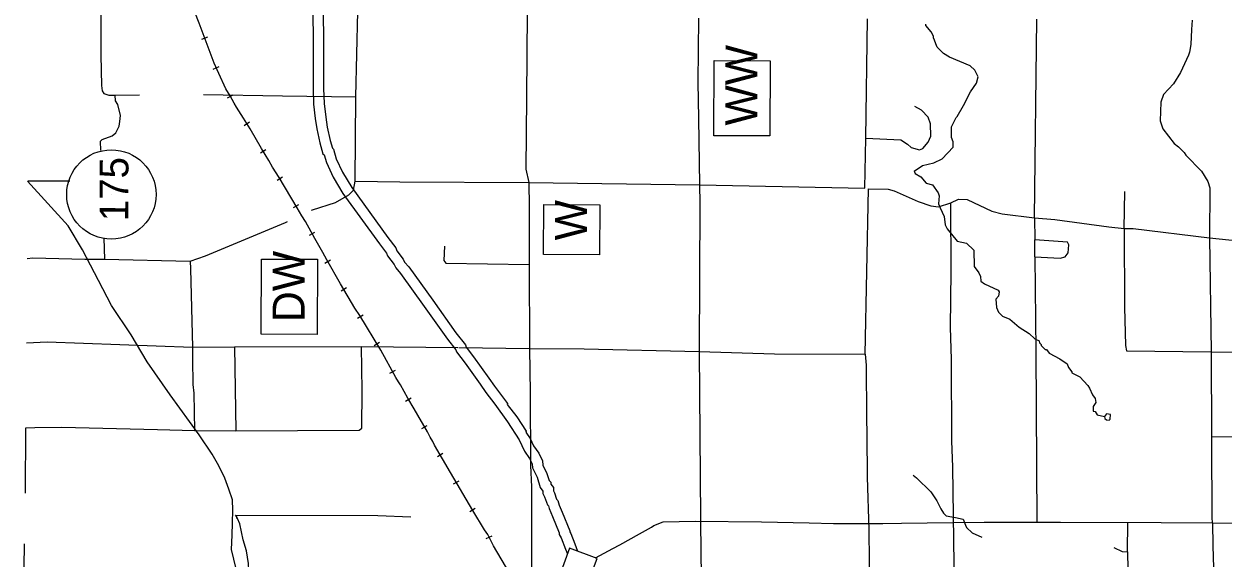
# Model space of a CAD drawing. Extents: x 299354 to 1325680, y 96128 to 228242.
# Drawn here: x 304317 to 341858, y 184619 to 201335 of the extents above; entities that cross this region are included whole.
import ezdxf

# ---------------------------------------------------------------- set-up
doc = ezdxf.new("R2010")
doc.units = 0
for name, color, linetype in [('Level 12', 7, 'Continuous'), ('Level 13', 7, 'Continuous'), ('Level 2', 7, 'Continuous'), ('Level 4', 7, 'Continuous'), ('Level 57', 7, 'Continuous')]:
    doc.layers.add(name, color=color, linetype=linetype)

msp = doc.modelspace()

# ---------------------------------------------------------------- linework, layer by layer
at = {"layer": 'Level 12'}
msp.add_line((307050, 195999), (307050, 195999), dxfattribs=at)
msp.add_circle((307050, 195999), 1398, dxfattribs=at)
at = {"layer": 'Level 13'}
for p, q in [((326757, 199059), (326757, 199059)), ((321428, 194930), (321428, 194930)), ((312597, 192846), (312597, 192846))]:
    msp.add_line(p, q, dxfattribs=at)
for points in [[(327649, 197829), (325899, 197836), (325908, 200191), (327658, 200184)], [(322322, 194108), (320572, 194115), (320579, 195685), (322329, 195678)], [(313489, 191616), (311739, 191623), (311749, 193978), (313499, 193971)]]:
    msp.add_lwpolyline(points, close=True, dxfattribs=at)
at = {"layer": 'Level 2'}
for points in [[(313351, 203218), (313361, 199311), (313373, 198825), (313429, 198373), (313477, 198048), (313575, 197612), (313668, 197275), (313703, 197239), (313776, 197000), (313988, 196538), (314292, 196030), (315434, 194453), (315660, 194160), (315692, 194078), (315894, 193804), (315947, 193697), (316096, 193527), (316840, 192493), (317567, 191467), (317828, 191139), (317843, 191073), (318119, 190721), (318585, 190062), (318768, 189800), (319049, 189430), (319444, 188880), (319803, 188314), (319976, 187960), (320132, 187734), (320212, 187570), (320228, 187437), (320366, 187146), (320470, 186825), (320550, 186716), (320549, 186643), (320604, 186532), (320694, 186281), (320722, 186252), (320746, 186166), (320848, 185922), (321063, 185410), (321063, 185351), (321119, 185247), (321255, 184900), (321318, 184747)], [(313681, 203219), (313691, 199315), (313703, 198849), (313756, 198417), (313802, 198108), (313896, 197692), (313964, 197445), (313995, 197413), (314085, 197117), (314281, 196692), (314568, 196212), (315699, 194651), (315951, 194324), (315984, 194238), (316178, 193975), (316224, 193881), (316355, 193732), (317109, 192685), (317831, 191665), (318131, 191288), (318148, 191220), (318383, 190918), (318855, 190252), (319035, 189994), (319314, 189626), (319438, 189454), (319437, 189424), (319737, 189035), (320022, 188585), (320021, 188553), (320148, 188360), (320261, 188128), (320418, 187901), (320534, 187664), (320549, 187529), (320673, 187268), (320746, 187044), (320799, 186990), (320799, 186935), (320881, 186823), (320880, 186718), (320908, 186661), (320980, 186461), (321018, 186422), (321059, 186274), (321152, 186050), (321394, 185475), (321394, 185434), (321419, 185387), (321545, 185065), (321632, 184836)], [(320061, 201695), (320037, 199037), (320016, 196795), (320112, 196378)], [(325414, 201513), (325395, 199513), (325418, 198380), (325449, 196296)], [(310952, 184277), (310809, 184886), (310825, 185331), (310839, 185723), (310854, 186115), (310836, 186444), (310724, 186774), (310602, 187115), (310416, 187509), (310199, 187873), (309795, 188471), (308893, 189723), (308168, 190760), (307672, 191603), (307050, 192523), (306648, 193301), (306143, 194262), (305698, 195020), (304423, 196414)], [(320112, 196378), (320122, 195611), (320122, 193803)], [(325449, 196296), (325460, 195721), (325434, 191079)], [(320122, 193803), (320131, 191177)], [(304400, 191358), (305046, 191381), (309590, 191223)], [(309590, 191223), (310899, 191228)], [(310899, 191228), (314877, 191242)], [(314877, 191242), (317889, 191205)], [(320131, 191177), (320151, 189785), (320164, 187519), (320191, 186852), (320193, 183502), (320223, 183429)], [(325434, 191079), (325478, 185862), (325479, 185735)], [(322196, 184621), (322733, 184920), (322960, 185035), (323572, 185371), (323949, 185584), (324016, 185634), (324317, 185748), (325318, 185772), (327386, 185753), (328879, 185723), (329646, 185699), (331189, 185702), (331765, 185714), (333374, 185732)], [(333408, 185732), (334359, 185740), (335459, 185738), (336744, 185744), (339896, 185732), (341506, 185717)], [(341543, 184308), (341516, 185000), (341506, 185717)], [(341506, 185717), (351087, 185630), (354390, 185584), (354916, 185594)]]:
    msp.add_lwpolyline(points, dxfattribs=at)
msp.add_lwpolyline([(321066, 184064), (321929, 183746), (322247, 184609), (321384, 184927)], close=True, dxfattribs=at)
at = {"layer": 'Level 4'}
for p, q in [((309879, 200862), (310066, 200931)), ((310238, 199922), (310421, 200004)), ((310687, 199018), (310860, 199119)), ((311206, 198159), (311375, 198267)), ((311715, 197300), (311885, 197404)), ((312233, 196447), (312405, 196549)), ((338730, 194934), (338755, 196091)), ((312743, 195587), (312915, 195689)), ((313244, 194724), (313418, 194822)), ((313733, 193851), (313907, 193951)), ((314235, 192984), (314407, 193086)), ((314752, 192127), (314923, 192231)), ((315271, 191273), (315442, 191376)), ((315761, 190406), (315936, 190502)), ((316257, 189533), (316429, 189637)), ((316761, 188672), (316934, 188771)), ((317251, 187800), (317423, 187901)), ((317756, 186937), (317929, 187038)), ((318262, 186075), (318435, 186176)), ((318780, 185226), (318958, 185317))]:
    msp.add_line(p, q, dxfattribs=at)
for points in [[(306709, 204458), (306719, 201866), (306722, 200357), (306746, 199407), (306761, 199240), (306819, 199156), (306969, 199105), (307169, 199103)], [(310411, 199782), (310264, 200109), (309800, 201363), (309507, 202116), (309385, 202450), (309352, 202534), (309271, 202759), (309198, 202993)], [(314699, 199052), (314757, 201726)], [(318358, 186110), (317660, 187300), (317159, 188154), (317102, 188271), (317019, 188405), (316938, 188565), (316519, 189293), (316322, 189620), (316092, 190039), (316031, 190137), (315952, 190265), (315480, 191122), (314819, 192209), (314672, 192444), (314220, 193206), (313793, 193948), (313670, 194178), (313416, 194622), (313120, 195149), (313013, 195325), (312866, 195577), (312299, 196532), (312092, 196856), (311979, 197060), (311749, 197437), (311396, 198048), (311182, 198384), (310968, 198727), (310894, 198861), (310763, 199087), (310632, 199305), (310411, 199782), (310264, 200109), (309800, 201363)], [(330650, 197757), (330701, 201499)], [(335931, 195268), (336005, 201484)], [(340859, 201457), (340839, 201165), (340818, 200690), (340783, 200457), (340748, 200358), (340502, 199818), (340281, 199462), (339970, 199123), (339884, 198890), (339862, 198299), (339943, 198057), (340298, 197595), (340430, 197494), (340612, 197309), (340661, 197225), (341149, 196729), (341354, 196402), (341419, 196201), (341405, 194643)], [(310632, 199305), (310411, 199782)], [(306719, 197373), (306713, 197666), (306764, 197715), (307074, 197829), (307191, 197928), (307293, 198135), (307320, 198285), (307338, 198468), (307249, 198811), (307184, 198928), (307169, 199103)], [(307169, 199103), (307933, 199121)], [(309932, 199123), (312406, 199089), (314699, 199052)], [(312092, 196856), (311979, 197060), (311749, 197437), (311396, 198048), (311182, 198384), (310968, 198727), (310894, 198861), (310763, 199087), (310632, 199305)], [(314675, 196410), (314699, 199052)], [(330650, 197757), (331750, 197706), (331957, 197570), (332073, 197469), (332331, 197400), (332432, 197433), (332600, 197631), (332685, 197822), (332672, 198206), (332607, 198415), (332393, 198633), (332185, 198752)], [(330619, 196199), (330650, 197757)], [(313793, 193948), (313670, 194178), (313416, 194622), (313120, 195149), (313013, 195325), (312866, 195577), (312299, 196532), (312092, 196856)], [(304434, 196428), (304634, 196426), (305748, 196429)], [(313316, 195510), (313341, 195522), (314060, 195749), (314479, 195987), (314622, 196136), (314675, 196410)], [(314675, 196410), (316076, 196398), (320112, 196378)], [(320112, 196378), (325449, 196296)], [(325449, 196296), (330619, 196199)], [(330637, 190999), (330735, 196173)], [(330735, 196173), (331352, 196168), (331535, 196116), (332291, 195776), (332682, 195647), (332923, 195612), (333308, 195733)], [(332400, 183208), (332468, 183290), (332602, 183373), (333236, 183400), (333420, 183449), (333422, 183674), (333374, 187466), (333348, 188291), (333338, 190833), (333306, 191850), (333322, 193583), (333308, 195733)], [(333308, 195733), (333551, 195848), (333818, 195845), (334599, 195480), (334923, 195394), (335931, 195268)], [(335931, 195268), (335941, 194576)], [(335931, 195268), (336564, 195212), (338255, 194988), (338730, 194934)], [(309514, 193915), (309991, 194078), (312494, 195122), (312565, 195155)], [(338730, 194934), (338741, 192467), (338780, 191275), (338812, 191108)], [(338730, 194934), (339014, 194932), (341405, 194643)], [(306811, 194627), (306838, 193973)], [(335936, 194043), (335941, 194576)], [(335936, 194043), (336737, 194002), (336887, 194051), (336980, 194175), (336999, 194425), (336958, 194508), (335941, 194576)], [(341405, 194643), (341455, 191068)], [(341405, 194643), (343421, 194433)], [(317467, 194385), (317446, 193927), (317512, 193843), (320122, 193803)], [(304418, 193992), (304595, 194010), (306221, 193978), (306838, 193973)], [(306838, 193973), (309514, 193915)], [(309514, 193915), (309521, 193669)], [(315480, 191122), (314819, 192209), (314672, 192444), (314220, 193206), (313793, 193948)], [(335936, 194043), (335968, 191101)], [(309521, 193669), (309590, 191223)], [(309590, 191223), (309586, 190848), (309595, 190048), (309626, 189781), (309649, 188614)], [(310899, 191228), (310941, 188602)], [(310941, 188602), (314803, 188617), (314887, 188683), (314898, 189866), (314877, 191242)], [(315480, 191122), (315480, 191122)], [(316031, 190137), (315952, 190265), (315480, 191122)], [(317925, 191204), (320131, 191177)], [(320131, 191177), (321840, 191162), (325434, 191079)], [(335968, 191101), (336001, 185734)], [(338812, 191108), (341455, 191068)], [(325434, 191079), (327794, 191008), (330637, 190999)], [(330637, 190999), (330668, 190657), (330669, 189032), (330689, 188473), (330694, 187148), (330745, 185506), (330753, 184523), (330803, 182747), (330849, 180472)], [(341455, 191068), (341464, 188409)], [(341455, 191068), (342539, 191058), (342797, 191006), (344082, 191044)], [(317102, 188271), (317019, 188405), (316938, 188565), (316519, 189293), (316322, 189620), (316092, 190039), (316031, 190137)], [(304360, 186651), (304379, 188695), (304654, 188709), (305497, 188718), (308498, 188641), (309649, 188614)], [(309649, 188614), (310941, 188602)], [(341464, 188409), (343991, 188436), (344029, 188473)], [(318826, 185356), (318727, 185498), (318358, 186110), (317660, 187300), (317159, 188154), (317102, 188271)], [(341464, 188409), (341464, 188239)], [(341464, 188239), (341474, 185884), (341489, 185717)], [(311348, 182957), (311351, 183223), (311357, 183973), (311376, 184190), (311352, 184240), (311337, 184448), (311274, 184849), (311177, 185192), (311065, 185684), (310999, 185852), (310966, 185877), (310983, 185885), (310967, 185919), (310934, 185960), (315387, 185954), (316421, 185911)], [(319376, 184359), (319006, 185004), (318826, 185356), (318727, 185498), (318358, 186110)], [(325479, 185735), (325545, 180520)], [(338837, 184808), (338845, 185741)], [(320508, 182422), (320296, 182826), (320041, 183270), (319376, 184359), (319006, 185004), (318826, 185356)], [(304317, 183812), (304322, 184320), (304334, 185059)], [(338413, 184945), (338670, 184826), (338837, 184808)], [(338837, 184808), (338871, 183133)]]:
    msp.add_lwpolyline(points, dxfattribs=at)
at = {"layer": 'Level 57'}
for points in [[(332167, 196727), (332428, 196908), (332779, 196988), (333038, 197119), (333384, 197474), (333385, 197641), (333328, 197783), (333331, 198116), (333476, 198407), (333509, 198440), (333712, 198780), (333925, 199211), (334111, 199484), (334163, 199684), (334065, 199893), (333916, 200028), (333592, 200164), (333268, 200300), (333085, 200410), (332887, 200612), (332838, 200713), (332806, 200830), (332765, 200905), (332765, 200955), (332700, 201089), (332535, 201290), (332535, 201324)], [(332167, 196727), (332200, 196652), (332374, 196550), (332539, 196349), (332739, 196297), (332912, 196054), (332944, 195953), (332925, 195703), (332974, 195578)], [(332974, 195578), (332991, 195578)], [(332974, 195578), (333105, 195310), (333136, 195051), (333201, 194918), (333507, 194540), (333806, 194470), (334029, 194252), (334041, 193743), (334190, 193550), (334239, 193433), (334254, 193283), (334370, 193199), (334793, 193003), (334826, 192953), (334808, 192820), (334724, 192720), (334738, 192462), (334804, 192311), (334928, 192193), (335160, 192091), (335450, 191847), (335765, 191644), (335939, 191476), (336071, 191416), (336087, 191350), (336137, 191299), (336137, 191266), (336261, 191148), (336302, 191148), (336385, 191030), (336725, 190852), (336949, 190700), (336998, 190583), (337097, 190449), (337096, 190415), (337345, 190288), (337601, 190019), (337651, 189935), (337749, 189726), (337831, 189609), (337847, 189492), (337762, 189359), (337761, 189218), (337827, 189200), (337893, 189100), (338118, 189048)], [(332138, 187215), (332237, 187134), (332683, 186689), (332873, 186404), (333004, 186161), (333086, 186027), (333169, 185943), (333460, 185890), (333693, 185838), (333766, 185645), (333799, 185579), (333981, 185410), (334280, 185274)]]:
    msp.add_lwpolyline(points, dxfattribs=at)
msp.add_lwpolyline([(338118, 189048), (338134, 188981), (338184, 188947), (338267, 188930), (338301, 188963), (338302, 189113), (338185, 189131)], close=True, dxfattribs=at)

# ---------------------------------------------------------------- texts
at = {"layer": 'Level 12'}
msp.add_text('175', height=900, rotation=89.767, dxfattribs=at).set_placement((307578, 195159))
at = {"layer": 'Level 13'}
for s, p in [('WW', (327253, 198152)), ('W', (321927, 194558)), ('DW', (313094, 192002))]:
    msp.add_text(s, height=1000, rotation=89.767, dxfattribs=at).set_placement(p)

doc.saveas('drawing.dxf')
